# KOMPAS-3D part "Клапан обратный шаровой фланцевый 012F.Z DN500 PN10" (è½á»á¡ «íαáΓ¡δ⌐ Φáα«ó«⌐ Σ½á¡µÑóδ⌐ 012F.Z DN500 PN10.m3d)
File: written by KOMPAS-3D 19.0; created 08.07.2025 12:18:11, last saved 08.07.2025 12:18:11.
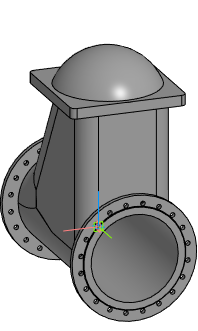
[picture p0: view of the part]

Document properties: Полное имя файла: E:\Dendor Работа Сачек\3D для проектировщиков\5.3 Тип 012F, 012F.Z Клапан обратный шаровой фланцевый\stp_Клапан обратный шаровой фланцевый 012F.Z PN10_16\Клапан обратный шаровой фланцевый 012F.Z DN500 PN10.m3d

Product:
- Part/product: Клапан обратный шаровой фланцевый 012F.Z DN500 PN10

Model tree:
1. Операция без истории:1  (labels: Клапан обратный шаровой фланцевый 012F.Z DN500 PN10)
